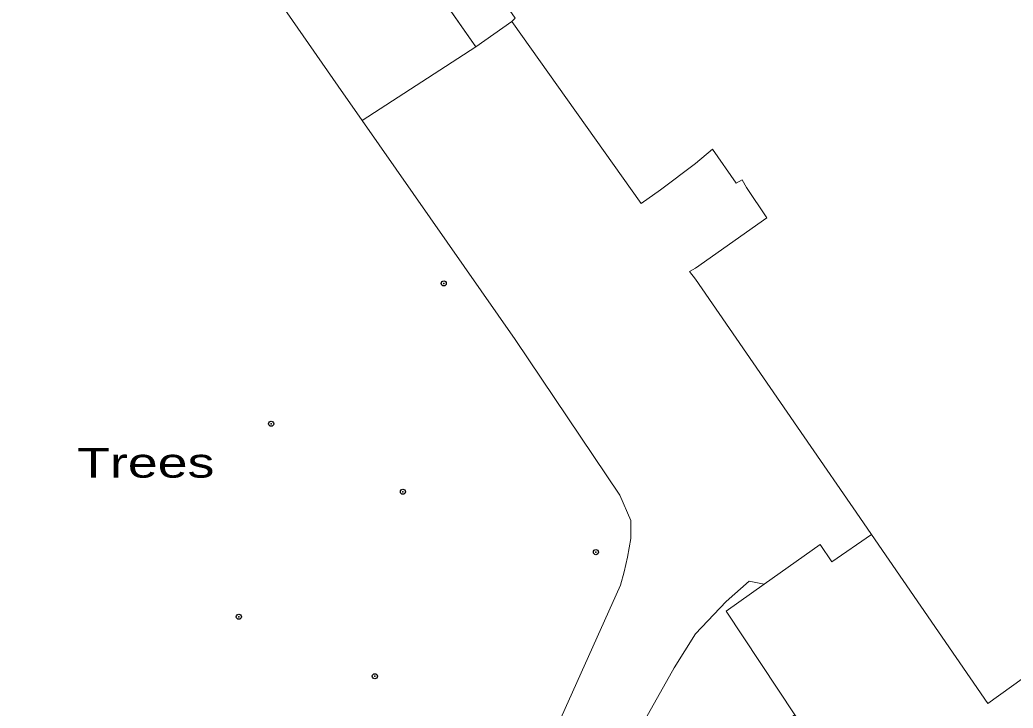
# Model space of a CAD drawing. Extents: x 528790 to 529292, y 179350 to 179856.
# Drawn here: x 528960.3 to 529018.7, y 179518.5 to 179559 of the extents above; entities that cross this region are included whole.
import ezdxf

# ---------------------------------------------------------------- set-up
doc = ezdxf.new("R2010")
doc.units = 0
doc.header["$LTSCALE"] = 0.6
doc.header["$PDMODE"] = 32
doc.header["$PDSIZE"] = 0.3
doc.layers.add('1', color=7, linetype='Continuous', lineweight=13)
doc.layers.add('2', color=7, linetype='Continuous', lineweight=13)
doc.layers.add('3', color=7, linetype='Continuous')
doc.layers.add('5', color=7, linetype='Continuous')

msp = doc.modelspace()

# ---------------------------------------------------------------- linework, layer by layer
at = {"layer": '1'}
for points in [[(528931.35, 179623.2), (528938.9, 179612.3), (528947.3, 179600.3), (528956.2, 179587.65), (528961.7, 179579.8), (528970.3, 179567.6), (528979, 179555.1), (528980.41, 179553.09), (528987.09, 179557.41), (528960.75, 179595.05), (528951.8, 179607.65), (528923.7, 179647.65), (528923.8, 179647.7), (528926.05, 179649.3), (528922.2, 179655.1)], [(528991.4, 179516.4), (528995.6, 179525.75), (528995.8, 179526.55), (528996, 179527.4), (528996.2, 179528.5), (528996.2, 179529.55), (528995.55, 179531.05), (528989.4, 179540.2), (528980.41, 179553.09), (528979, 179555.1), (528970.3, 179567.6)], [(528996.35, 179516.65), (528998.75, 179520.9), (529000, 179522.9), (529001.8, 179524.8), (529003.15, 179526), (529004.05, 179525.81), (529007.33, 179528.14), (529008.022, 179527.132), (529010.352, 179528.732), (529009.658, 179529.739), (529006.39, 179534.48), (529000, 179543.75), (528999.65, 179544.2), (529000, 179544.4), (529004.2, 179547.35), (529003, 179549.15), (529002.75, 179549.6), (529002.4, 179549.4), (529001, 179551.4), (529000, 179550.55), (528997.95, 179549), (528996.8, 179548.2), (528989.2, 179558.9), (528987.09, 179557.41), (528980.41, 179553.09), (528989.4, 179540.2), (528995.55, 179531.05), (528996.2, 179529.55), (528996.2, 179528.5), (528996, 179527.4), (528995.8, 179526.55), (528995.6, 179525.75), (528991.4, 179516.4)], [(528989.4, 179559.1), (528989.2, 179558.9)], [(528989.2, 179558.9), (528996.8, 179548.2), (528997.95, 179549), (529000, 179550.55), (529001, 179551.4), (529002.4, 179549.4), (529002.75, 179549.6), (529003, 179549.15), (529004.2, 179547.35), (529000, 179544.4), (528999.65, 179544.2), (529000, 179543.75), (529006.39, 179534.48), (529009.658, 179529.739), (529010.352, 179528.732), (529017.2, 179518.8), (529022, 179522.25)], [(528978.75, 179488.05), (528979.9, 179486.3), (528984.9, 179489.65), (528991.5, 179500), (529000, 179513.3), (529000.85, 179514.7), (529005.85, 179518.14), (529001.81, 179524.22), (529004.05, 179525.81)], [(529004.05, 179525.81), (529003.15, 179526), (529001.8, 179524.8), (529000, 179522.9), (528998.75, 179520.9), (528996.35, 179516.65)]]:
    msp.add_lwpolyline(points, dxfattribs=at)
for points in [[(528960.75, 179595.05), (528987.09, 179557.41), (528989.2, 179558.9), (528989.4, 179559.1), (528963.25, 179596.65)], [(529010.352, 179528.732), (529008.022, 179527.132), (529007.33, 179528.14), (529004.05, 179525.81), (529001.81, 179524.22), (529005.85, 179518.14), (529009.04, 179513.34), (529015.84, 179517.83), (529028.02, 179500.54), (529034, 179504.75), (529030.07, 179510.45), (529027.29, 179514.43), (529026.2, 179516), (529024.35, 179518.8), (529022, 179522.25), (529017.2, 179518.8)]]:
    msp.add_lwpolyline(points, close=True, dxfattribs=at)
at = {"layer": '2'}
for p, q in [((528960.75, 179595.05), (528987.09, 179557.41)), ((528987.09, 179557.41), (528989.2, 179558.9)), ((528989.4, 179559.1), (528989.2, 179558.9)), ((528987.09, 179557.41), (528980.41, 179553.09))]:
    msp.add_line(p, q, dxfattribs=at)
for points in [[(528909.7, 179652.25), (528910.75, 179651.4), (528912, 179650.3), (528915.8, 179645.2), (528922.05, 179636.3), (528931.35, 179623.2), (528938.9, 179612.3), (528947.3, 179600.3), (528956.2, 179587.65), (528961.7, 179579.8), (528970.3, 179567.6), (528979, 179555.1), (528980.41, 179553.09)], [(529010.352, 179528.732), (529009.658, 179529.739), (529006.39, 179534.48), (529000, 179543.75), (528999.65, 179544.2), (529000, 179544.4), (529004.2, 179547.35), (529003, 179549.15), (529002.75, 179549.6), (529002.4, 179549.4), (529001, 179551.4), (529000, 179550.55), (528997.95, 179549), (528996.8, 179548.2), (528989.2, 179558.9)], [(528980.41, 179553.09), (528989.4, 179540.2), (528995.55, 179531.05), (528996.2, 179529.55), (528996.2, 179528.5), (528996, 179527.4), (528995.8, 179526.55), (528995.6, 179525.75), (528991.4, 179516.4), (528989.7, 179513.25), (528987.8, 179510.15), (528986.2, 179507.8)], [(529004.05, 179525.81), (529007.33, 179528.14), (529008.022, 179527.132), (529010.352, 179528.732)], [(529022, 179522.25), (529017.2, 179518.8), (529010.352, 179528.732)], [(529004.05, 179525.81), (529003.15, 179526), (529001.8, 179524.8), (529000, 179522.9), (528998.75, 179520.9), (528996.35, 179516.65)], [(529004.05, 179525.81), (529001.81, 179524.22), (529005.85, 179518.14)]]:
    msp.add_lwpolyline(points, dxfattribs=at)
at = {"layer": '3'}
for p in [(528985.2, 179543.5), (528975.05, 179535.25), (528982.8, 179531.25), (528994.15, 179527.7), (528973.15, 179523.9), (528981.15, 179520.4)]:
    msp.add_point(p, dxfattribs=at)

# ---------------------------------------------------------------- texts
at = {"layer": '5', "width": 1.35}
msp.add_text('Trees', height=1.75, dxfattribs=at).set_placement((528963.64, 179532.08))

doc.saveas('drawing.dxf')
